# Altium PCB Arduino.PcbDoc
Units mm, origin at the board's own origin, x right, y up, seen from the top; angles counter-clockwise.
Board outline 57.28 x 53.59 mm, 2 copper layers (Top Layer, Bottom Layer); 34 components, 41 nets, 113 pads, 21 vias.
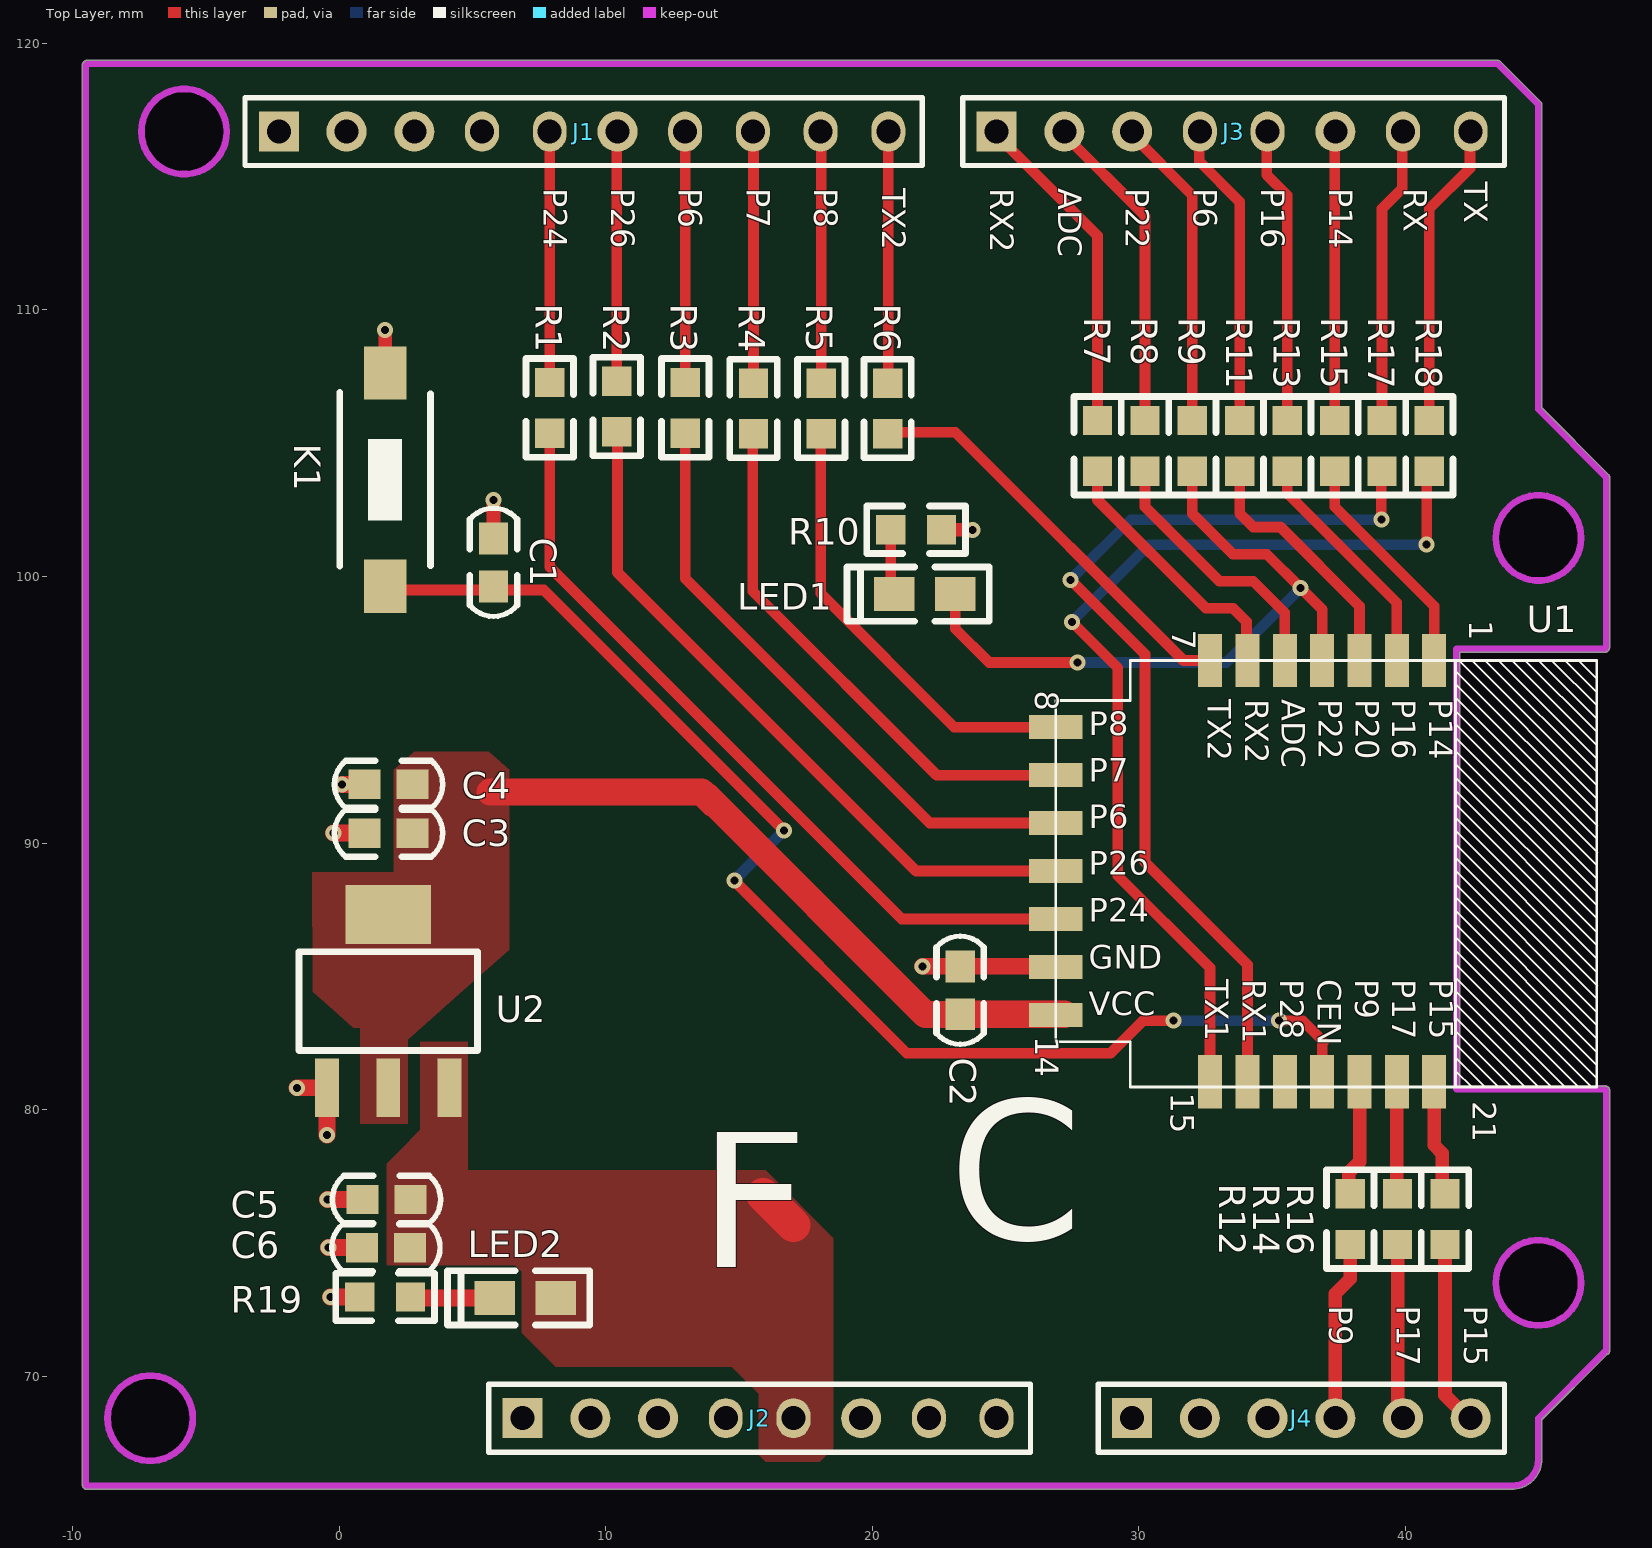
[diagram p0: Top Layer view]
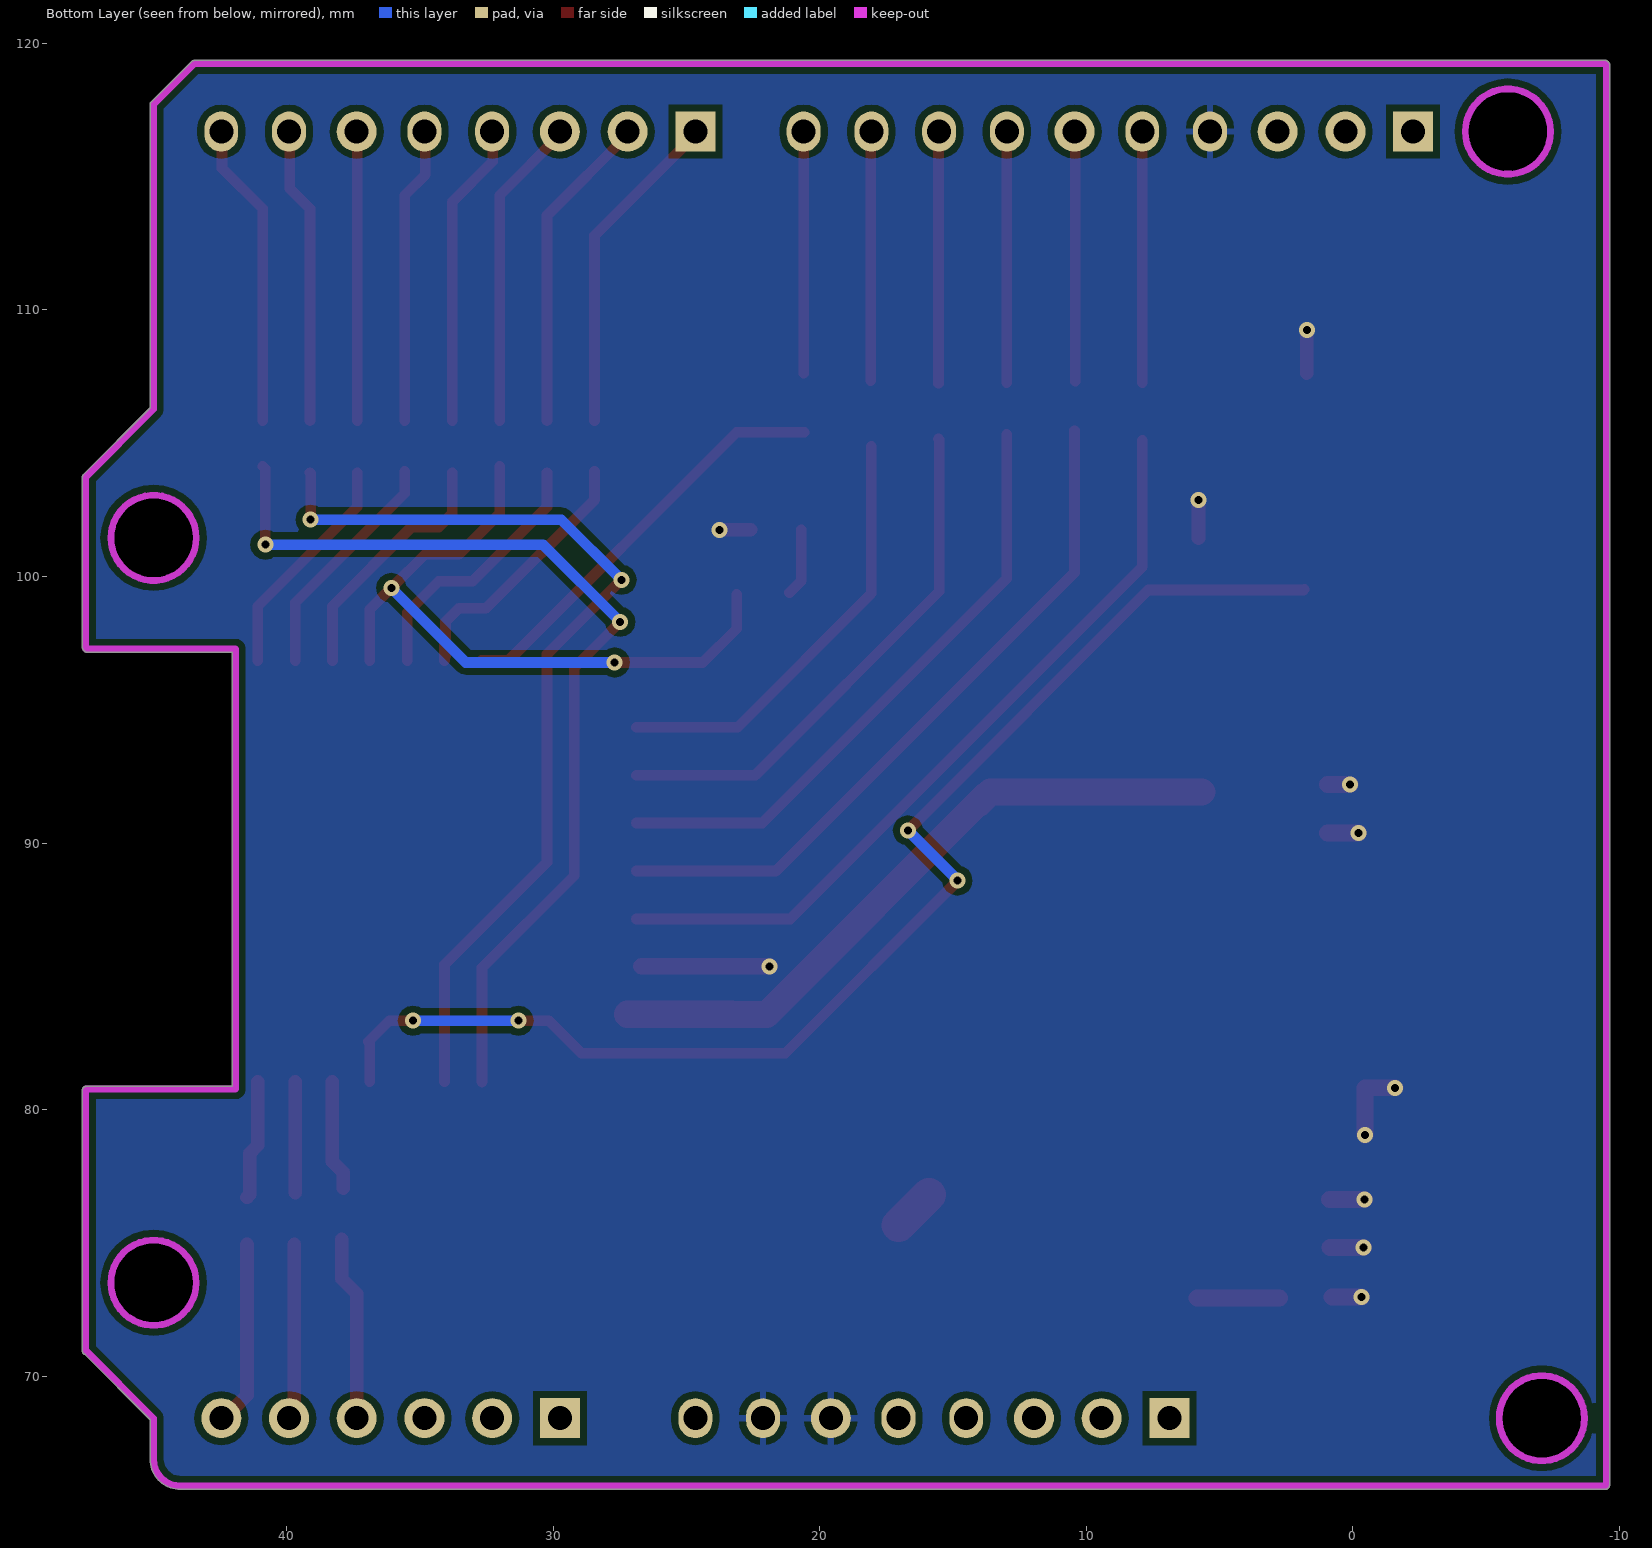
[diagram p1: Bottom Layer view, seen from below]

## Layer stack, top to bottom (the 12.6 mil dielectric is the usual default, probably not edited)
Top Layer: signal copper 0.0356
Dielectric: dielectric 0.32, FR-4, Dk 4.8
Bottom Layer: signal copper 0.0356

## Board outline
-9.576,65.811 ccw(c-9.474,65.888) -9.474,65.76 43.983,65.76 ccw(c43.983,66.888) 45.111,66.888 ccw(c44.983,66.888) 45.111,66.888 45.111,68.375 47.555,70.819 ccw(c47.523,70.942) 47.651,70.942 47.651,80.747 ccw(c47.523,80.747) 47.523,80.874 42.037,80.874 42.037,97.155 47.473,97.155 ccw(c47.473,97.282) 47.563,97.192 47.613,97.243 47.613,97.242 ccw(c47.523,97.333) 47.651,97.333 47.651,103.708 ccw(c47.523,103.708) 47.65,103.721 ccw(c47.523,103.734) 47.651,103.734 ccw(c47.523,103.734) 47.613,103.824 45.111,106.326 45.111,117.704 ccw(c44.983,117.704) 45.073,117.794 43.549,119.318 43.55,119.317 ccw(c43.459,119.228) 43.459,119.355 -9.474,119.355 ccw(c-9.474,119.228) -9.576,119.304 ccw(c-9.5,119.202) -9.627,119.202 -9.627,65.913 ccw(c-9.5,65.913)
cut-out: -8.687,68.428 ccw(c-7.087,68.428) -7.087,66.828 ccw(c-7.087,68.428) -5.487,68.428 ccw(c-7.087,68.428) -7.087,70.028 ccw(c-7.087,68.428)
cut-out: -7.417,116.688 ccw(c-5.817,116.688) -5.817,115.088 ccw(c-5.817,116.688) -4.217,116.688 ccw(c-5.817,116.688) -5.817,118.288 ccw(c-5.817,116.688)
cut-out: 43.383,101.448 ccw(c44.983,101.448) 44.983,99.848 ccw(c44.983,101.448) 46.583,101.448 ccw(c44.983,101.448) 44.983,103.048 ccw(c44.983,101.448)
cut-out: 43.383,73.508 ccw(c44.983,73.508) 44.983,71.908 ccw(c44.983,73.508) 46.583,73.508 ccw(c44.983,73.508) 44.983,75.108 ccw(c44.983,73.508)
cut-out: -7.417,116.688 ccw(c-5.817,116.688) -5.817,115.088 ccw(c-5.817,116.688) -4.217,116.688 ccw(c-5.817,116.688) -5.817,118.288 ccw(c-5.817,116.688)

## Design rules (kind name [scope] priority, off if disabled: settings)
Clearance Clearance_3 [WithinRoom('CP2102')] p1: gap=0.178
Clearance [HasFootprint('QFN-28') vs InNetClass('All Nets')] p2: gap=0.178
Clearance Clearance_2 [All] p3: gap=0.254
Clearance Clearance_1 [All] p4: gap=0.254
HoleSize [All] p1: absolutevalues=TRUE maxlimit=3 minlimit=0.025 maxpercent=80.000 minpercent=20.000
HoleToHoleClearance [All] p1: gap=0 allowstackedmicrovias=TRUE
MinimumSolderMaskSliver [All] p1: minsoldermaskwidth=0
PolygonConnect [InComponent('J5')] p1: connectstyle=Direct reliefconductorwidth=0.254 reliefentries=4 polygonreliefangle="90 Angle"
PolygonConnect PolygonConnect_6 [InNet('+3.3V')] p2: connectstyle=Direct reliefconductorwidth=0.508 reliefentries=4 polygonreliefangle="90 Angle"
PolygonConnect PolygonConnect_5 [InNet('+3.3V') vs IsPad] p3: connectstyle=Direct reliefconductorwidth=0.254 reliefentries=4 polygonreliefangle="90 Angle"
PolygonConnect PolygonConnect_4 [InNet('+3.3V') vs IsVia] p4: connectstyle=Direct reliefconductorwidth=0.254 reliefentries=4 polygonreliefangle="90 Angle"
PolygonConnect PolygonConnect_3 [InNet('+5V') vs IsVia] p5: connectstyle=Direct reliefconductorwidth=0.254 reliefentries=4 polygonreliefangle="90 Angle"
PolygonConnect PolygonConnect_2 [InNet('+5V') vs IsPad] p6: connectstyle=Direct reliefconductorwidth=0.254 reliefentries=4 polygonreliefangle="90 Angle"
PolygonConnect PolygonConnect_1 [InNet('GND') vs IsVia] p7: connectstyle=Direct reliefconductorwidth=0.254 reliefentries=4 polygonreliefangle="90 Angle"
RoutingVias [All] p1: holewidth=0.2 width=1.27 viastyle="Through Hole" minholewidth=0.2 minwidth=0.2 maxholewidth=1.2 maxwidth=1.27
SilkToSilkClearance [All] p1: silktosilkclearance=0
SilkscreenOverComponentPads [All] p1: minsilkscreentomaskgap=0
SolderMaskExpansion [All] p1: expansion=0.102
Width [All] p1: maxlimit=6 minlimit=0.254 preferedwidth=0.254
23 further rules are at their usual default settings.

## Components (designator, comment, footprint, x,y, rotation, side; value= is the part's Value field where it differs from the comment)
C1 "20p" C0603 5.791,100.533 r270 top
C2 "0.1u" C0603 23.292,84.48 r90 top
C3 "0.1u" C0603 1.854,90.373 r180 top
C4 "0.1u" C0603 1.854,92.202 r180 top
C5 "0.1u" C0603 1.778,76.632 r180 top
C6 "0.1u" C0603 1.753,74.828 r180 top
J1 "CON10" HDR1X10Z -2.261,116.688 r0 top
J2 "CON8" HDR1X8Z 6.883,68.428 r0 top
J3 "CON8" HDR1X8Z 24.663,116.688 r0 top
J4 "CON6" HDR1X6Z 29.743,68.428 r0 top
K1 "reset" KEY-MM-Half-SMT 1.727,103.632 r0 top
LED1 "LED" D0805 20.828,99.339 r0 top
LED2 "LED" D0805 5.842,72.94 r0 top
R1 "RES1" R0603 7.899,106.324 r90 top
R2 "RES1" R0603 10.414,106.375 r90 top
R3 "RES1" R0603 12.979,106.324 r90 top
R4 "RES1" R0603 15.545,106.299 r90 top
R5 "RES1" R0603 18.085,106.299 r90 top
R6 "RES1" R0603 20.574,106.299 r90 top
R7 "RES1" R0603 28.448,104.902 r90 top
R8 "RES1" R0603 30.226,104.902 r90 top
R9 "RES1" R0603 32.004,104.902 r90 top
R10 "RES1" R0603 21.641,101.752 r180 top
R11 "RES1" R0603 33.782,104.902 r90 top
R12 "RES1" R0603 37.922,75.895 r270 top
R13 "RES1" R0603 35.56,104.902 r90 top
R14 "RES1" R0603 39.7,75.895 r270 top
R15 "RES1" R0603 37.338,104.902 r90 top
R16 "RES1" R0603 41.478,75.895 r270 top
R17 "RES1" R0603 39.116,104.902 r90 top
R18 "RES1" R0603 40.894,104.902 r90 top
R19 "RES1" R0603 1.727,72.974 r0 top
U1 "WIFI_BLE_CBU" WIFI_BLE_CBU 26.873,88.951 r270 top
U2 "LM1117IMPX-3.3" SOT-223 -0.457,80.823 r0 top

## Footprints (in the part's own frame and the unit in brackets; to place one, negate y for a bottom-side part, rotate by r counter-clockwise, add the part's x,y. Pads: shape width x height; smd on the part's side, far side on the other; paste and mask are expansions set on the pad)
C0603 [mm]
  rect 1.2x1.1 smd: 1(-0.9,0) 2(0.9,0)
  silkscreen extent -2.03,-0.89 2.03,0.89, body extent -0.87,-0.48 0.87,0.48, height 0.85
D0805 [mil]
  rect 60x50 smd: 1(0,0) 2(90,0)
  silkscreen extent -70,-40 140,40
HDR1X6Z [mm]
  rect 1.5x1.5 hole 0.9: 1(0,0)
  round 1.5 hole 0.9: 2(2.54,0) 3(5.08,0) 4(7.62,0) 5(10.16,0) 6(12.7,0)
  silkscreen extent -1.27,-1.27 13.97,1.27
HDR1X8Z [mm]
  rect 1.5x1.5 hole 0.9: 1(0,0)
  round 1.5 hole 0.9: 2(2.54,0) 3(5.08,0) 6(12.7,0)
  oval 1.27x1.5 hole 0.9: 4(7.62,0) 5(10.16,0) 7(15.24,0) 8(17.78,0)
  silkscreen extent -1.27,-1.27 19.05,1.27
HDR1X10Z [mm] "Conne"
  rect 1.5x1.5 hole 0.9: 1(0,0)
  round 1.5 hole 0.9: 2(2.54,0) 3(5.08,0) 6(12.7,0)
  oval 1.27x1.5 hole 0.9: 4(7.62,0) 5(10.16,0) 7(15.24,0) 8(17.78,0) 9(20.32,0) 10(22.86,0)
  silkscreen extent -1.27,-1.27 24.13,1.27
KEY-MM-Half-SMT [mm]
  rect 1.6x2 smd: 1(0,4) 2(0,-4)
  silkscreen extent -1.7,-3.25 1.7,3.28
R0603 [mm]
  rect 1.1x1.1 smd: 1(-0.95,0) 2(0.95,0)
  silkscreen extent -1.85,-0.89 1.85,0.89, body extent -0.85,-0.48 0.85,0.48, height 0.6
SOT-223 [mm]
  rect 0.9x2.2 smd: 1(0,0) 2(2.3,0) 3(4.6,0)
  rect 3.2x2.2 smd: 4(2.3,6.5)
  silkscreen extent -1.05,1.4 5.65,5.1
WIFI_BLE_CBU [mm]
  rect 2x0.9 smd: 1(-7.9,14.2) 2(-7.9,12.8) 3(-7.9,11.4) 4(-7.9,10) 5(-7.9,8.6) 6(-7.9,7.2) 7(-7.9,5.8) 15(7.9,5.8) 16(7.9,7.2) 17(7.9,8.6) 18(7.9,10) 19(7.9,11.4) 20(7.9,12.8) 21(7.9,14.2)
  rect 0.9x2 smd: 8(-5.4,0) 9(-3.6,0) 10(-1.8,0) 11(0,0) 12(1.8,0) 13(3.6,0) 14(5.4,0)
  silkscreen extent -7.9,0 8.14,20.33

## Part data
J1: "Connector"
R1 R3 R4 R5 R6 R7 R8 R9 R11 R12 R13 R14 R15 R16 R17 R18 R19: "Resi"
U2: "800mA Low-Dropout Lin"

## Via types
v1: diameter 0.6, hole 0.3, Top Layer to Bottom Layer, 21 vias

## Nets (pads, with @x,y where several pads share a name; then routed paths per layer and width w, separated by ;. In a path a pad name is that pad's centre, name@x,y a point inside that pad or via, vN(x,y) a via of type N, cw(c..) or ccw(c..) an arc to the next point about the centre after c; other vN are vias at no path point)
+3.3V: C2.1 C3.1 C4.1 U1.14 U2.2 U2.4 | length 25.2
  Top Layer w1.016: 5.664,91.923 13.589,91.923 14.021,91.491 ; 13.818,91.745 21.996,83.566 C2.1@23.19,83.566 ; C2.1 U1.14@27.214,83.58
+5V: C5.1 C6.1 J2.5 LED2.2 U2.3 | length 1.6
  Top Layer w1.27: 15.9,76.81 17.043,75.667
ADC: R8.1 U1.5 | length 10
  Top Layer w0.4: R8.1@30.226,103.886 30.226,102.616 33.02,99.822 34.29,99.822 35.473,98.639 U1.5
GND: C1.1 C2.2 C3.2 C4.2 C5.2 C6.2 J1.4 J2.6 J2.7 K1.1 R10.1 R19.1 U1.13 U2.1 | length 17.6
  Top Layer w0.508: K1.1 v1(1.727,109.245) ; C1.1 v1(5.791,102.87) ; R10.1 v1(23.749,101.752)
  Top Layer w0.635: v1(-1.575,80.823) U2.1 v1(-0.457,79.045) ; v1(-0.432,76.632) C5.2 ; v1(-0.406,74.828) C6.2 ; v1(-0.33,72.974) R19.1 ; v1(-0.203,90.373) C3.2 ; v1(0.1,92.202) C4.2 ; v1(21.88,85.38) C2.2 U1.13@26.681,85.38
NetJ1_5: J1.5 R1.2 | length 9.4
  Top Layer w0.4: R1.2 J1.5@7.899,116.713
NetJ1_6: J1.6 R2.2 | length 9.3
  Top Layer w0.4: R2.2 J1.6@10.414,116.586
NetJ1_7: J1.7 R3.2 | length 9.3
  Top Layer w0.4: R3.2 12.979,116.535 J1.7@13.005,116.561
NetJ1_8: J1.8 R4.2 | length 9.3
  Top Layer w0.4: R4.2 J1.8@15.545,116.51
NetJ1_9: J1.9 R5.2 | length 9
  Top Layer w0.4: R5.2@18.085,107.351 J1.9@18.085,116.332
NetJ1_10: J1.10 R6.2 | length 9.1
  Top Layer w0.4: R6.2@20.599,107.62 J1.10
NetJ3_1: J3.1 R7.2 | length 12.3
  Top Layer w0.4: J3.1@24.638,116.586 28.448,112.776 R7.2
NetJ3_2: J3.2 R8.2 | length 12
  Top Layer w0.4: J3.2@27.178,116.586 30.226,113.538 R8.2
NetJ3_3: J3.3 R9.2 | length 11.7
  Top Layer w0.4: J3.3@29.718,116.586 32.004,114.3 R9.2
NetJ3_4: J3.4 R11.2 | length 11.4
  Top Layer w0.4: J3.4@32.258,116.586 32.258,115.57 33.782,114.046 R11.2
NetJ3_5: J3.5 R13.2 | length 11
  Top Layer w0.4: J3.5@34.798,116.586 34.798,115.062 35.56,114.3 R13.2
NetJ3_6: J3.6 R15.2 | length 10.8
  Top Layer w0.4: R15.2 37.338,116.332 J3.6@37.592,116.586
NetJ3_7: J3.7 R17.2 | length 11.3
  Top Layer w0.4: R17.2 39.116,113.792 39.878,114.554 J3.7@39.878,116.84
NetJ3_8: J3.8 R18.2 | length 11.6
  Top Layer w0.4: R18.2 40.894,113.792 42.418,115.316 J3.8@42.418,116.84
NetJ4_4: J4.4 R12.2 | length 6.9
  Top Layer w0.508: J4.4 37.363,73.101 37.922,73.66 R12.2@37.922,75.133
NetJ4_5: J4.5 R14.2 | length 6.5
  Top Layer w0.508: J4.5@39.7,68.402 R14.2
NetJ4_6: J4.6 R16.2 | length 6.9
  Top Layer w0.508: R16.2 41.478,69.291 J4.6@42.393,68.377
NetLED1_1: LED1.1 R10.2 | length 2.5
  Top Layer w0.4: R10.2 20.691,99.832 LED1.1@21.133,99.39
NetLED2_1: LED2.1 R19.2 | length 3.1
  Top Layer w0.635: R19.2@2.752,72.94 LED2.1
OUT_DATA: R13.1 U1.2 | length 9.3
  Top Layer w0.4: R13.1@35.56,103.632 35.56,103.124 ; R13.1 35.56,103.124 ; U1.2 39.673,99.011 35.56,103.124
P6: R3.1 U1.10 | length 23.1
  Top Layer w0.4: R3.1@12.979,105.334 12.979,99.924 22.152,90.751 U1.10
P6_KEY1: R11.1 U1.3 | length 9.5
  Top Layer w0.4: R11.1@33.782,103.886 33.782,102.362 34.29,101.854 35.306,101.854 38.273,98.887 U1.3
P7: R4.1 U1.9 | length 19.9
  Top Layer w0.4: R4.1@15.545,105.156 15.519,105.131 15.519,99.441 22.41,92.551 U1.9
P8: R5.1 U1.8 | length 16.4
  Top Layer w0.4: R5.1@18.059,104.877 18.059,99.365 23.073,94.351 U1.8
P9: R12.1 U1.19 | length 4.2
  Top Layer w0.508: R12.1@37.871,77.064 37.871,77.648 38.273,78.05 U1.19
P14: R15.1 U1.1 | length 8.6
  Top Layer w0.4: R15.1@37.338,103.886 37.338,102.616 41.073,98.881 U1.1
P15: R16.1 U1.21 | length 4.5
  Top Layer w0.508: U1.21 41.073,78.662 41.377,78.359 41.377,76.81 R16.1@41.478,76.708
P17: R14.1 U1.20 | length 4.2
  Top Layer w0.508: R14.1@39.673,76.887 U1.20
P22: LED1.2 R9.1 U1.4 | length 26
  Top Layer w0.4: LED1.2 23.114,98.044 24.384,96.774 24.638,96.774 v1(27.686,96.774) ; R9.1@32.004,104.14 32.004,102.362 33.528,100.838 34.798,100.838 v1(36.068,99.568) 36.873,98.763 U1.4
  Bottom Layer w0.4: v1(27.686,96.774) 33.274,96.774 v1(36.068,99.568)
P24: R1.1 U1.12 | length 29.2
  Top Layer w0.4: R1.1@7.899,105.105 7.899,100.355 21.104,87.151 U1.12
P26: R2.1 U1.11 | length 26.4
  Top Layer w0.4: R2.1@10.439,105.461 10.439,100.152 21.641,88.951 U1.11
P28: U1.17
RST: C1.2 K1.2 U1.18 | length 48.3
  Top Layer w0.4: K1.2@1.829,99.517 1.854,99.492 7.671,99.492 v1(16.688,90.475) ; v1@14.808,88.595 21.285,82.118 28.931,82.118 30.15,83.337 v1(31.293,83.337) ; v1(35.255,83.337) 36.144,83.337 36.932,82.55 ; U1.18 36.873,82.456
  Bottom Layer w0.4: v1@14.808,88.595 v1(16.688,90.475) ; v1(31.293,83.337) v1(35.255,83.337)
  other v1: 14.834,88.595
RX2: R7.1 U1.6 | length 10.7
  Top Layer w0.4: R7.1 28.448,102.87 32.512,98.806 33.528,98.806 34.036,98.298 U1.6@34.036,97.028 ; U1.6 U1.6@34.073,97.753
TX2: R6.1 U1.7 | length 15.6
  Top Layer w0.4: R6.1@20.574,105.41 23.114,105.41 31.673,96.851 U1.7
WRX: R17.1 U1.16 | length 35.9
  Top Layer w0.4: v1(27.432,99.873) 30.226,97.079 30.226,89.281 34.073,85.434 U1.16 ; v1(39.091,102.133) 39.091,103.861 R17.1@39.116,103.886
  Bottom Layer w0.4: v1(27.432,99.873) 29.693,102.133 v1(39.091,102.133)
WTX: R18.1 U1.15 | length 36.9
  Top Layer w0.4: v1(27.483,98.298) 29.21,96.571 29.21,88.773 32.664,85.319 32.664,81.042 U1.15 ; v1(40.792,101.194) 40.792,104.038 R18.1@40.894,104.14
  Bottom Layer w0.4: v1(27.483,98.298) 30.378,101.194 v1(40.792,101.194)
pads on no net: J1.1 J1.2 J1.3 J2.1 J2.2 J2.3 J2.4 J2.8 J4.1 J4.2 J4.3

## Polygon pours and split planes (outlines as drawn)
+3.3V on Top Layer "Keep-Out Layer-No Net" (solid, pour order 6): 0.787,79.477 0.787,83.075 0.533,83.075 -0.229,83.75 -0.991,84.425 -0.991,85.999 -0.991,87.349 -0.229,88.023 1.041,88.023 1.803,88.023 2.057,88.248 2.057,89.373 2.057,92.746 2.311,92.971 2.819,93.421 3.835,93.421 5.613,93.421 5.867,93.196 6.375,92.746 6.375,86.899 6.375,85.999 4.343,84.2 2.565,82.625 2.565,79.926 2.565,79.477
+5V on Top Layer "Keep-Out Layer-No Net" (solid, pour order 10): 1.778,77.724 1.778,74.168 6.604,74.168 6.858,73.914 6.858,72.898 6.858,71.628 7.62,70.866 8.128,70.358 11.43,70.358 14.732,70.358 15.748,69.342 15.748,67.31 15.748,67.056 16.002,66.802 16.764,66.802 18.034,66.802 18.288,67.056 18.542,67.31 18.542,68.326 18.542,75.184 16.002,77.724
+5V on Top Layer "Keep-Out Layer-No Net" (solid, pour order 12): 3.048,82.55 3.048,79.502 3.048,79.248 2.286,78.486 1.778,77.978 1.778,77.47 1.778,74.168 3.556,74.168 3.556,77.724 3.81,77.978 4.826,78.994 4.826,82.55
+5V on Top Layer "Keep-Out Layer-No Net" (solid, pour order 14): 4.826,79.502 4.826,76.962 3.556,76.962 2.54,77.978
+3.3V on Top Layer "Keep-Out Layer-No Net" (solid, pour order 16): -1.016,86.868 -1.016,88.9 2.794,88.9 3.048,88.646 3.048,86.36
GND on Bottom Layer "Keep-Out Layer-No Net" (solid, remove dead copper, pour order 7): -9.576,65.811 ccw(c-9.474,65.888) -9.474,65.76 43.983,65.76 ccw(c43.983,66.888) 45.111,66.888 ccw(c44.983,66.888) 45.111,66.888 45.111,68.375 47.555,70.819 ccw(c47.523,70.942) 47.651,70.942 47.651,80.747 ccw(c47.523,80.747) 47.523,80.874 42.037,80.874 42.037,97.155 47.473,97.155 ccw(c47.473,97.282) 47.563,97.192 47.613,97.243 47.613,97.242 ccw(c47.523,97.333) 47.651,97.333 47.651,103.708 ccw(c47.523,103.708) 47.65,103.721 ccw(c47.523,103.734) 47.651,103.734 ccw(c47.523,103.734) 47.613,103.824 45.111,106.326 45.111,117.704 ccw(c44.983,117.704) 45.073,117.794 43.549,119.318 43.55,119.317 ccw(c43.459,119.228) 43.459,119.355 -9.474,119.355 ccw(c-9.474,119.228) -9.576,119.304 ccw(c-9.5,119.202) -9.627,119.202 -9.627,65.913 ccw(c-9.5,65.913)

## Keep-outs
Keep-Out Layer:
  circle w0.254: c44.983,73.508 r1.6
  circle w0.254: c-5.817,116.688 r1.6
  circle w0.254: c-7.087,68.428 r1.6
  circle w0.254: c44.983,101.448 r1.6
  lines w0.254: 47.498,80.772 41.91,80.772 41.91,97.282 47.523,97.282 47.523,103.657 47.523,103.734 44.983,106.274 44.983,117.704 43.459,119.228 -9.474,119.228 -9.5,119.202 -9.5,65.888 43.983,65.888 ccw(c43.983,66.888) 44.983,66.888 44.983,68.428 47.523,70.968 47.523,80.772

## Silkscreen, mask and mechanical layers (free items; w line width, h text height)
Top Overlay:
  text "TX" at 41.91,114.808 h1.5 r270
  text "P24" at 7.366,114.554 h1.5 r270
  text "P26" at 9.906,114.554 h1.5 r270
  text "P6" at 12.446,114.554 h1.5 r270
  text "P7" at 14.986,114.554 h1.5 r270
  text "P8" at 17.526,114.554 h1.5 r270
  text "TX2" at 20.066,114.554 h1.5 r270
  text "RX2" at 24.13,114.554 h1.5 r270
  text "ADC" at 26.67,114.554 h1.5 r270
  text "P22" at 29.21,114.554 h1.5 r270
  text "P6" at 31.75,114.554 h1.5 r270
  text "P16" at 34.29,114.554 h1.5 r270
  text "P14" at 36.83,114.554 h1.5 r270
  text "RX" at 39.624,114.554 h1.5 r270
  text "C" at 22.86,73.406 h9
  text "P9" at 36.83,72.644 h1.5 r270
  text "P17" at 39.37,72.644 h1.5 r270
  text "P15" at 41.91,72.644 h1.5 r270
  text "F" at 13.462,72.39 h9
Mechanical 1:
  circle w0.254: c44.983,101.448 r1.6
  circle w0.254: c-7.087,68.428 r1.6
  circle w0.254: c-5.817,116.688 r1.6
  circle w0.254: c44.983,73.508 r1.6
  lines w0.254: -9.5,65.913 -9.5,119.202 ; -9.474,65.888 43.983,65.888 ccw(c43.983,66.888) 44.983,66.888 44.983,68.428 47.523,70.968 ; -9.474,119.228 43.459,119.228 44.983,117.704 44.983,106.274 47.523,103.734 ; 41.91,80.747 47.447,80.747 ; 41.91,80.772 41.91,97.282 47.473,97.282 47.523,97.333 47.523,103.708 ; 46.838,80.747 47.523,80.747 47.523,70.942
